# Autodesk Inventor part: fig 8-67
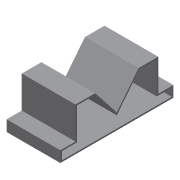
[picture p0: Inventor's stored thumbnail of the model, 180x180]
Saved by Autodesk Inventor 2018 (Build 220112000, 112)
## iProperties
Shininess: 77.0
Length Units: 11269
Angle Units: 11279
Time Units: 11290
Mass Units: 11283
Length Display Precision: 3
Angle Display Precision: 2
Created: 2002-01
Part Number: fig 8-67
Document SubType Name: Modeling
Designer: ***
Density: 1 g/cm^3
Material: Generic
Appearance: Default
Density: 0.0
Volumn: 0.0
Area: 0.0
PropertySet Name: Model Information
Control State: 0
Master: False
Checked Out: False
Author: ***
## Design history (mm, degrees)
node "Sketch1"
sketch "Sketch2"
  geometry: L1 (0, 0)-(-14.184, 17.961); L2 (-14.184, 17.961)-(-26.987, 17.961); L3 (-26.987, 17.961)-(-26.987, -2.947); L4 (-26.987, -2.947)-(-36.842, -2.947); L5 (-36.842, -2.947)-(-36.842, -10.132); L6 (26.987, 17.961)-(26.987, -2.947); L7 (14.184, 17.961)-(26.987, 17.961); L8 (26.987, -2.947)-(36.842, -2.947); L9 (36.842, -10.132)-(-36.842, -10.132); L10 (36.842, -2.947)-(36.842, -10.132); L11 (0, 0)-(14.184, 17.961)
  constraints: 22 end point, 2 horizontal, 2 parallel, 1 perpendicular
extrude "Extrusion1" new body sketch "Sketch2" distance "d0" = 35; taper "d1" = 0 deg
shell "Shell3" dims "d13" = 1
body "Solid1"
